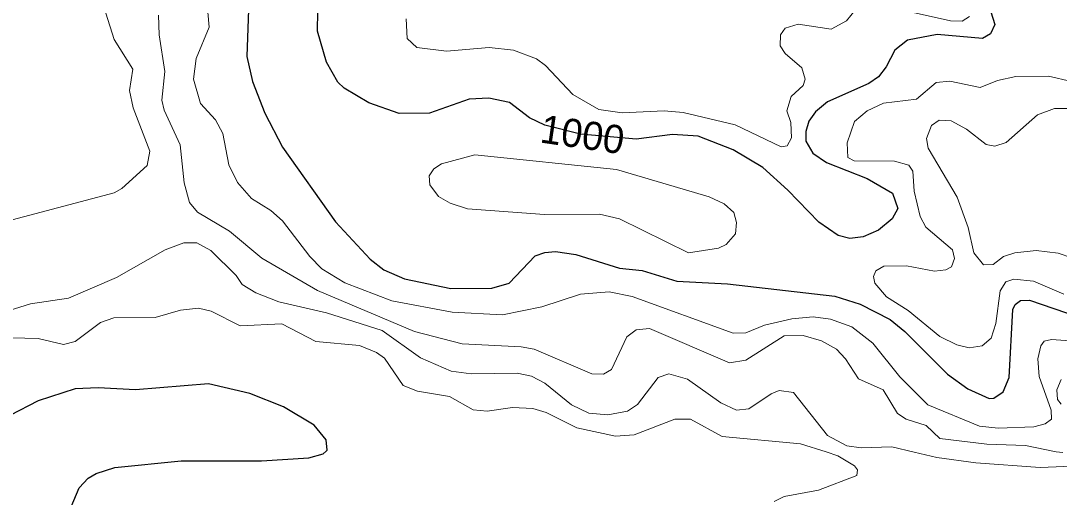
# Model space of a CAD drawing. Extents: x 473.9 to 500, y 7733.1 to 7760.8.
# Drawn here: x 479.198 to 482.147, y 7743.401 to 7744.754 of the extents above; entities that cross this region are included whole.
import ezdxf
from ezdxf.enums import TextEntityAlignment as Align

# ---------------------------------------------------------------- set-up
doc = ezdxf.new("R2010")
doc.units = 0
doc.header["$LTSCALE"] = 0.032
doc.layers.add('1', color=7, linetype='Continuous', lineweight=25)
doc.layers.add('2', color=7, linetype='Continuous', lineweight=13)
doc.layers.add('61', color=7, linetype='Continuous')

msp = doc.modelspace()

# ---------------------------------------------------------------- linework, layer by layer
at = {"layer": '1'}
for points in [[(479.8454, 7744.8125), (479.8399, 7744.6521), (479.8557, 7744.5809), (479.8904, 7744.4916), (479.9414, 7744.3954), (480.0912, 7744.1828), (480.1901, 7744.0771), (480.2291, 7744.0469), (480.2871, 7744.0208), (480.4193, 7743.9942), (480.5357, 7743.9945), (480.5845, 7744.0094), (480.6588, 7744.0862), (480.686, 7744.0961), (480.7167, 7744.0986), (480.774, 7744.0899), (480.8977, 7744.0511), (480.9621, 7744.0448), (481.0608, 7744.0143), (481.2049, 7744.0071), (481.5094, 7743.9724), (481.5812, 7743.9492), (481.6669, 7743.9055), (481.7085, 7743.8717), (481.8293, 7743.7502), (481.8872, 7743.7087), (481.9475, 7743.6815), (481.9609, 7743.6826), (481.9875, 7743.7008), (482.0042, 7743.7416), (482.0154, 7743.9346), (482.0213, 7743.9483), (482.0366, 7743.9596), (482.0626, 7743.9603), (482.2363, 7743.9015)], [(481.9525, 7744.7793), (481.9639, 7744.7429), (481.9513, 7744.7163), (481.9289, 7744.7035), (481.8003, 7744.7146), (481.7158, 7744.699), (481.6802, 7744.6704), (481.6556, 7744.6233), (481.6333, 7744.595), (481.6059, 7744.5759), (481.489, 7744.5237), (481.4542, 7744.495), (481.4354, 7744.4688), (481.4268, 7744.4398), (481.4276, 7744.4117), (481.4468, 7744.3775), (481.4863, 7744.3513), (481.6015, 7744.3057), (481.6732, 7744.2643), (481.688, 7744.2208), (481.6728, 7744.1913), (481.6338, 7744.1597), (481.5904, 7744.1409), (481.5523, 7744.1361), (481.5188, 7744.1445), (481.4638, 7744.1817), (481.3764, 7744.273), (481.3049, 7744.3371), (481.2207, 7744.3876), (481.1213, 7744.4259), (481.0489, 7744.4308), (480.9456, 7744.4172), (480.7872, 7744.432), (480.6857, 7744.4571), (480.6427, 7744.4786), (480.5861, 7744.5222), (480.5267, 7744.5338), (480.4713, 7744.5308), (480.3581, 7744.4913), (480.2727, 7744.4902), (480.1865, 7744.5211), (480.1166, 7744.5626), (480.0983, 7744.5795), (480.0658, 7744.6364), (480.0408, 7744.7245), (480.0414, 7744.781)], [(479.3407, 7743.3742), (479.3634, 7743.4279), (479.3888, 7743.4552), (479.4115, 7743.4689), (479.4651, 7743.4853), (479.6532, 7743.5046), (479.8813, 7743.5047), (480.0156, 7743.5128), (480.0567, 7743.5244), (480.0647, 7743.532), (480.0674, 7743.5346), (480.0647, 7743.564), (480.0312, 7743.6055), (479.9436, 7743.6576), (479.8478, 7743.6959), (479.7304, 7743.7232), (479.5236, 7743.7065)], [(479.5236, 7743.7065), (479.4171, 7743.7121), (479.3526, 7743.7088), (479.2476, 7743.6747), (479.1671, 7743.633)]]:
    msp.add_lwpolyline(points, dxfattribs=at)
at = {"layer": '2'}
for points in [[(479.1414, 7744.1801), (479.4627, 7744.2654), (479.485, 7744.278), (479.5569, 7744.343), (479.5638, 7744.384), (479.5166, 7744.5064), (479.5061, 7744.5562), (479.5157, 7744.6168), (479.463, 7744.7005), (479.4394, 7744.775), (479.4435, 7744.8311), (479.4926, 7744.896), (479.5162, 7744.9675)], [(479.9413, 7744.1862), (479.908, 7744.2153), (479.8526, 7744.2491), (479.813, 7744.2946), (479.789, 7744.3445), (479.7715, 7744.4336), (479.7512, 7744.4726), (479.7079, 7744.519), (479.6879, 7744.5879), (479.6959, 7744.6463), (479.7327, 7744.7358), (479.7216, 7744.8638)], [(481.6724, 7744.7903), (481.838, 7744.7534), (481.8711, 7744.7526), (481.8919, 7744.7659)], [(479.5889, 7744.7697), (479.5909, 7744.7136), (479.6065, 7744.6099), (479.5984, 7744.5285), (479.6051, 7744.5), (479.6501, 7744.4014), (479.6619, 7744.2936), (479.6769, 7744.2376), (479.6999, 7744.2103), (479.7904, 7744.1563), (479.8827, 7744.0795), (480.0404, 7743.9879), (480.3158, 7743.8714), (480.4509, 7743.8371), (480.6186, 7743.8286), (480.6561, 7743.8215), (480.8195, 7743.7516), (480.8527, 7743.7511), (480.8754, 7743.7639), (480.9184, 7743.8568), (480.945, 7743.8769), (480.983, 7743.88), (481.2104, 7743.7829), (481.2565, 7743.79), (481.3652, 7743.8597), (481.42, 7743.86), (481.472, 7743.8454), (481.5142, 7743.8217), (481.5402, 7743.794), (481.5764, 7743.7371), (481.647, 7743.7063), (481.6871, 7743.6392), (481.7119, 7743.6228), (481.7693, 7743.6051), (481.8079, 7743.5683), (481.941, 7743.5516), (482.0507, 7743.5482), (482.138, 7743.5305), (482.1569, 7743.5288)], [(480.2919, 7744.759), (480.2955, 7744.7032), (480.3221, 7744.6775), (480.4068, 7744.6674), (480.5279, 7744.6775), (480.5971, 7744.6704), (480.6619, 7744.6452), (480.6879, 7744.6263), (480.7652, 7744.5443), (480.8397, 7744.5022), (480.9053, 7744.492), (481.0246, 7744.4984), (481.079, 7744.4936), (481.2265, 7744.4584), (481.3573, 7744.3956), (481.3744, 7744.3989), (481.3867, 7744.4217), (481.3844, 7744.4653), (481.373, 7744.4983), (481.3854, 7744.5389), (481.4194, 7744.57), (481.4251, 7744.5884), (481.4154, 7744.6199), (481.3687, 7744.6609), (481.354, 7744.6829), (481.3548, 7744.7135), (481.3686, 7744.7326), (481.4053, 7744.7443), (481.4995, 7744.7301), (481.5426, 7744.7533), (481.5677, 7744.7838)], [(482.1596, 7743.9779), (482.0733, 7744.0143), (482.0176, 7744.02), (481.9951, 7744.0129), (481.9795, 7743.9876), (481.9671, 7743.8942), (481.9534, 7743.8528), (481.9275, 7743.8314), (481.891, 7743.8251), (481.8562, 7743.8335), (481.8081, 7743.8577), (481.7174, 7743.931), (481.6561, 7743.9702), (481.6227, 7744.0089), (481.6191, 7744.0281), (481.6256, 7744.0439), (481.6483, 7744.0575), (481.7131, 7744.0577), (481.7925, 7744.0434), (481.8246, 7744.0471), (481.8406, 7744.0554), (481.8489, 7744.0792), (481.8437, 7744.1038), (481.768, 7744.1678), (481.7518, 7744.1977), (481.7349, 7744.27), (481.7313, 7744.3268), (481.7193, 7744.3443), (481.6788, 7744.3552), (481.5643, 7744.3558), (481.5469, 7744.3655), (481.5441, 7744.4073), (481.5657, 7744.4678), (481.601, 7744.4978), (481.6476, 7744.5196), (481.7414, 7744.5311), (481.7977, 7744.5788), (481.8364, 7744.582), (481.922, 7744.5644), (481.9719, 7744.5841), (482.0235, 7744.5956), (482.1162, 7744.5965), (482.1815, 7744.5817)], [(482.2215, 7744.0677), (482.1435, 7744.0937), (482.0813, 7744.1012), (482.0203, 7744.0955), (481.9885, 7744.0846), (481.9589, 7744.0618), (481.9321, 7744.0607), (481.9039, 7744.0947), (481.8878, 7744.167), (481.8566, 7744.2532), (481.7747, 7744.3924), (481.7703, 7744.4199), (481.7837, 7744.4564), (481.8059, 7744.4716), (481.8398, 7744.4699), (481.8831, 7744.4456), (481.9393, 7744.4023), (481.9641, 7744.3974), (481.9961, 7744.4081), (482.0854, 7744.4866), (482.1333, 7744.5049), (482.1966, 7744.5048)], [(482.2175, 7743.8423), (482.1247, 7743.8495), (482.1037, 7743.844), (482.0942, 7743.8312), (482.0862, 7743.7945), (482.0899, 7743.7441), (482.1242, 7743.6483), (482.1245, 7743.6225), (482.107, 7743.6093), (482.0751, 7743.6008), (481.9731, 7743.5971), (481.9208, 7743.6031), (481.7737, 7743.6632), (481.6945, 7743.7435), (481.6173, 7743.839), (481.5581, 7743.8852), (481.4976, 7743.9066), (481.4482, 7743.9131), (481.3876, 7743.9076), (481.3099, 7743.8898), (481.2569, 7743.8682), (481.2208, 7743.8668), (480.9337, 7743.9715), (480.8688, 7743.9846), (480.7873, 7743.9774), (480.6775, 7743.9416), (480.5654, 7743.9195), (480.4232, 7743.9263), (480.2511, 7743.9584), (480.1181, 7744.0096), (480.0525, 7744.0494), (480.0186, 7744.0847), (479.9413, 7744.1862)], [(482.2051, 7743.4902), (482.0922, 7743.4853), (481.9104, 7743.4988), (481.7989, 7743.5142), (481.7353, 7743.5294), (481.6712, 7743.5448), (481.5846, 7743.5416), (481.5432, 7743.5468), (481.4886, 7743.577), (481.3926, 7743.6987), (481.3515, 7743.704), (481.3288, 7743.6951), (481.2653, 7743.6519), (481.2305, 7743.6483), (481.1862, 7743.6689), (481.0915, 7743.7361), (481.0377, 7743.7513), (481.0074, 7743.7411), (480.9488, 7743.665), (480.9208, 7743.6457), (480.8652, 7743.6349), (480.8112, 7743.6403), (480.7619, 7743.6636), (480.6863, 7743.7249), (480.6483, 7743.7449), (480.607, 7743.7537), (480.477, 7743.7515), (480.4197, 7743.7589), (480.3329, 7743.7972), (480.224, 7743.8744), (480.066, 7743.9248), (479.9304, 7743.9563), (479.8649, 7743.9816), (479.8267, 7744.005), (479.8093, 7744.0304), (479.7373, 7744.1019), (479.6973, 7744.123), (479.6611, 7744.123), (479.6082, 7744.1036), (479.4696, 7744.0246), (479.3337, 7743.9666), (479.2255, 7743.95), (479.1494, 7743.9269)], [(479.1328, 7743.8544), (479.2474, 7743.852), (479.3193, 7743.8349), (479.352, 7743.8438), (479.4239, 7743.8971), (479.4619, 7743.9106), (479.5798, 7743.9113), (479.6516, 7743.9327), (479.702, 7743.9379), (479.7384, 7743.9299), (479.821, 7743.8876), (479.9391, 7743.8932), (480.0354, 7743.8434), (480.16, 7743.8317), (480.2084, 7743.8122), (480.2307, 7743.7961), (480.2833, 7743.7184), (480.3243, 7743.7027), (480.4154, 7743.6871), (480.4824, 7743.6491), (480.5226, 7743.6454), (480.5945, 7743.6565), (480.6519, 7743.6533), (480.6898, 7743.6423), (480.7767, 7743.5983), (480.8871, 7743.5746), (480.9396, 7743.5786), (481.0554, 7743.6228), (481.0999, 7743.6229), (481.1892, 7743.5737), (481.4119, 7743.5529), (481.4846, 7743.5298), (481.5184, 7743.5191), (481.5651, 7743.4901), (481.5739, 7743.4787), (481.5718, 7743.4631), (481.4628, 7743.4215), (481.3652, 7743.4033), (481.3373, 7743.3891)], [(482.152, 7743.6656), (482.1422, 7743.6792), (482.14, 7743.7062), (482.1525, 7743.7356)]]:
    msp.add_lwpolyline(points, dxfattribs=at)
msp.add_lwpolyline([(480.8978, 7744.1912), (480.8411, 7744.2049), (480.685, 7744.2034), (480.4661, 7744.2203), (480.4172, 7744.2363), (480.3836, 7744.2547), (480.3596, 7744.2879), (480.3575, 7744.3136), (480.3712, 7744.3336), (480.3924, 7744.3477), (480.4872, 7744.373), (480.8893, 7744.3311), (481.1523, 7744.2537), (481.1953, 7744.2338), (481.2225, 7744.2095), (481.2306, 7744.1816), (481.227, 7744.1485), (481.2012, 7744.1189), (481.1792, 7744.1087), (481.0936, 7744.0948)], close=True, dxfattribs=at)

# ---------------------------------------------------------------- texts
at = {"layer": '61'}
msp.add_text('1000', height=0.08, rotation=351.787, dxfattribs=at).set_placement((480.7872, 7744.3916), align=Align.CENTER)

doc.saveas('drawing.dxf')
